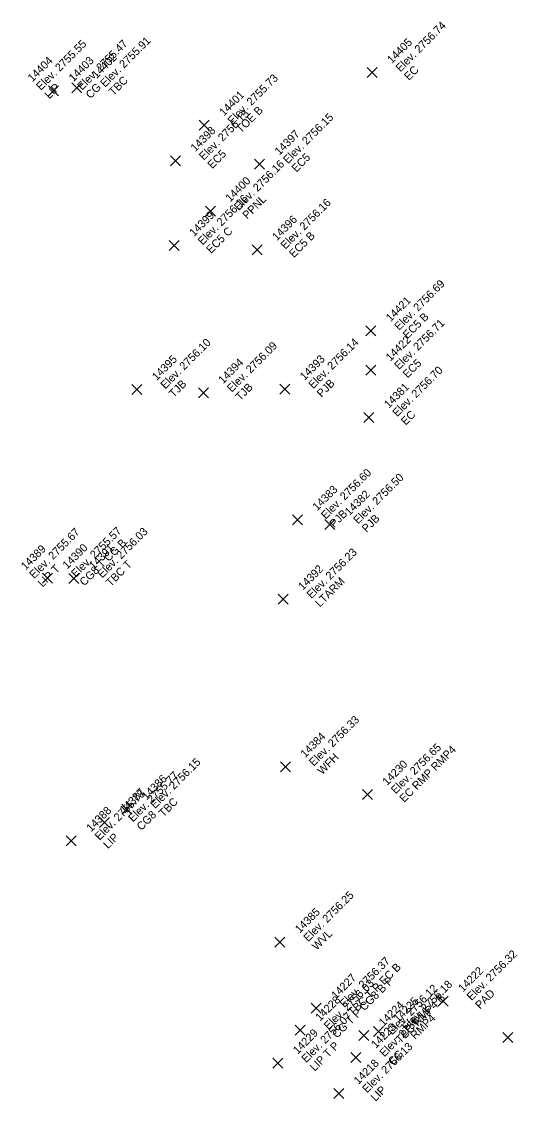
# Model space of a CAD drawing. Extents: x 2493999 to 2503109, y 700767 to 706646.
# Drawn here: x 2502320.41 to 2502335.28, y 703212 to 703244.38 of the extents above; entities that cross this region are included whole.
import ezdxf

# ---------------------------------------------------------------- set-up
doc = ezdxf.new("R2010")
doc.units = 0
doc.layers.add('ALG_CL_BLUE_Horiz', color=7, linetype='Continuous')
doc.layers.add('DES_SURFACE_Existing-Ground', color=7, linetype='Continuous')

msp = doc.modelspace()

# ---------------------------------------------------------------- linework, layer by layer
at = {"layer": 'ALG_CL_BLUE_Horiz'}
for points in [[(2502330.92, 703242.852), (2502330.77, 703243.002), (2502330.92, 703242.852), (2502330.77, 703242.702), (2502330.92, 703242.852), (2502331.07, 703242.702), (2502330.92, 703242.852), (2502331.07, 703243.002)], [(2502321.373, 703242.306), (2502321.223, 703242.456), (2502321.373, 703242.306), (2502321.223, 703242.156), (2502321.373, 703242.306), (2502321.523, 703242.156), (2502321.373, 703242.306), (2502321.523, 703242.456)], [(2502322.064, 703242.399), (2502321.914, 703242.549), (2502322.064, 703242.399), (2502321.914, 703242.249), (2502322.064, 703242.399), (2502322.214, 703242.249), (2502322.064, 703242.399), (2502322.214, 703242.549)], [(2502325.885, 703241.275), (2502325.735, 703241.425), (2502325.885, 703241.275), (2502325.735, 703241.125), (2502325.885, 703241.275), (2502326.035, 703241.125), (2502325.885, 703241.275), (2502326.035, 703241.425)], [(2502325.025, 703240.205), (2502324.875, 703240.355), (2502325.025, 703240.205), (2502324.875, 703240.055), (2502325.025, 703240.205), (2502325.175, 703240.055), (2502325.025, 703240.205), (2502325.175, 703240.355)], [(2502327.546, 703240.101), (2502327.396, 703240.251), (2502327.546, 703240.101), (2502327.396, 703239.951), (2502327.546, 703240.101), (2502327.696, 703239.951), (2502327.546, 703240.101), (2502327.696, 703240.251)], [(2502326.073, 703238.698), (2502325.923, 703238.848), (2502326.073, 703238.698), (2502325.923, 703238.548), (2502326.073, 703238.698), (2502326.223, 703238.548), (2502326.073, 703238.698), (2502326.223, 703238.848)], [(2502324.987, 703237.664), (2502324.837, 703237.814), (2502324.987, 703237.664), (2502324.837, 703237.514), (2502324.987, 703237.664), (2502325.137, 703237.514), (2502324.987, 703237.664), (2502325.137, 703237.814)], [(2502327.471, 703237.539), (2502327.321, 703237.689), (2502327.471, 703237.539), (2502327.321, 703237.389), (2502327.471, 703237.539), (2502327.621, 703237.389), (2502327.471, 703237.539), (2502327.621, 703237.689)], [(2502330.883, 703235.106), (2502330.733, 703235.256), (2502330.883, 703235.106), (2502330.733, 703234.956), (2502330.883, 703235.106), (2502331.033, 703234.956), (2502330.883, 703235.106), (2502331.033, 703235.256)], [(2502330.879, 703233.927), (2502330.729, 703234.077), (2502330.879, 703233.927), (2502330.729, 703233.777), (2502330.879, 703233.927), (2502331.029, 703233.777), (2502330.879, 703233.927), (2502331.029, 703234.077)], [(2502323.87, 703233.345), (2502323.72, 703233.495), (2502323.87, 703233.345), (2502323.72, 703233.195), (2502323.87, 703233.345), (2502324.02, 703233.195), (2502323.87, 703233.345), (2502324.02, 703233.495)], [(2502325.861, 703233.248), (2502325.711, 703233.398), (2502325.861, 703233.248), (2502325.711, 703233.098), (2502325.861, 703233.248), (2502326.011, 703233.098), (2502325.861, 703233.248), (2502326.011, 703233.398)], [(2502328.302, 703233.353), (2502328.152, 703233.503), (2502328.302, 703233.353), (2502328.152, 703233.203), (2502328.302, 703233.353), (2502328.452, 703233.203), (2502328.302, 703233.353), (2502328.452, 703233.503)], [(2502330.826, 703232.512), (2502330.676, 703232.662), (2502330.826, 703232.512), (2502330.676, 703232.362), (2502330.826, 703232.512), (2502330.976, 703232.362), (2502330.826, 703232.512), (2502330.976, 703232.662)], [(2502328.683, 703229.441), (2502328.533, 703229.591), (2502328.683, 703229.441), (2502328.533, 703229.291), (2502328.683, 703229.441), (2502328.833, 703229.291), (2502328.683, 703229.441), (2502328.833, 703229.591)], [(2502329.651, 703229.297), (2502329.501, 703229.447), (2502329.651, 703229.297), (2502329.501, 703229.147), (2502329.651, 703229.297), (2502329.801, 703229.147), (2502329.651, 703229.297), (2502329.801, 703229.447)], [(2502321.189, 703227.693), (2502321.039, 703227.843), (2502321.189, 703227.693), (2502321.039, 703227.543), (2502321.189, 703227.693), (2502321.339, 703227.543), (2502321.189, 703227.693), (2502321.339, 703227.843)], [(2502321.979, 703227.678), (2502321.829, 703227.828), (2502321.979, 703227.678), (2502321.829, 703227.528), (2502321.979, 703227.678), (2502322.129, 703227.528), (2502321.979, 703227.678), (2502322.129, 703227.828)], [(2502328.252, 703227.057), (2502328.102, 703227.207), (2502328.252, 703227.057), (2502328.102, 703226.907), (2502328.252, 703227.057), (2502328.402, 703226.907), (2502328.252, 703227.057), (2502328.402, 703227.207)], [(2502328.321, 703222.032), (2502328.171, 703222.182), (2502328.321, 703222.032), (2502328.171, 703221.882), (2502328.321, 703222.032), (2502328.471, 703221.882), (2502328.321, 703222.032), (2502328.471, 703222.182)], [(2502330.779, 703221.201), (2502330.629, 703221.351), (2502330.779, 703221.201), (2502330.629, 703221.051), (2502330.779, 703221.201), (2502330.929, 703221.051), (2502330.779, 703221.201), (2502330.929, 703221.351)], [(2502323.563, 703220.763), (2502323.413, 703220.913), (2502323.563, 703220.763), (2502323.413, 703220.613), (2502323.563, 703220.763), (2502323.713, 703220.613), (2502323.563, 703220.763), (2502323.713, 703220.913)], [(2502322.901, 703220.36), (2502322.751, 703220.51), (2502322.901, 703220.36), (2502322.751, 703220.21), (2502322.901, 703220.36), (2502323.051, 703220.21), (2502322.901, 703220.36), (2502323.051, 703220.51)], [(2502321.9, 703219.812), (2502321.75, 703219.962), (2502321.9, 703219.812), (2502321.75, 703219.662), (2502321.9, 703219.812), (2502322.05, 703219.662), (2502321.9, 703219.812), (2502322.05, 703219.962)], [(2502328.156, 703216.769), (2502328.006, 703216.919), (2502328.156, 703216.769), (2502328.006, 703216.619), (2502328.156, 703216.769), (2502328.306, 703216.619), (2502328.156, 703216.769), (2502328.306, 703216.919)], [(2502329.242, 703214.794), (2502329.092, 703214.944), (2502329.242, 703214.794), (2502329.092, 703214.644), (2502329.242, 703214.794), (2502329.392, 703214.644), (2502329.242, 703214.794), (2502329.392, 703214.944)], [(2502333.053, 703215.004), (2502332.903, 703215.154), (2502333.053, 703215.004), (2502332.903, 703214.854), (2502333.053, 703215.004), (2502333.203, 703214.854), (2502333.053, 703215.004), (2502333.203, 703215.154)], [(2502328.766, 703214.131), (2502328.616, 703214.281), (2502328.766, 703214.131), (2502328.616, 703213.981), (2502328.766, 703214.131), (2502328.916, 703213.981), (2502328.766, 703214.131), (2502328.916, 703214.281)], [(2502330.671, 703213.974), (2502330.521, 703214.124), (2502330.671, 703213.974), (2502330.521, 703213.824), (2502330.671, 703213.974), (2502330.821, 703213.824), (2502330.671, 703213.974), (2502330.821, 703214.124)], [(2502331.11, 703214.097), (2502330.96, 703214.247), (2502331.11, 703214.097), (2502330.96, 703213.947), (2502331.11, 703214.097), (2502331.26, 703213.947), (2502331.11, 703214.097), (2502331.26, 703214.247)], [(2502334.995, 703213.917), (2502334.845, 703214.067), (2502334.995, 703213.917), (2502334.845, 703213.767), (2502334.995, 703213.917), (2502335.145, 703213.767), (2502334.995, 703213.917), (2502335.145, 703214.067)], [(2502330.438, 703213.315), (2502330.288, 703213.465), (2502330.438, 703213.315), (2502330.288, 703213.165), (2502330.438, 703213.315), (2502330.588, 703213.165), (2502330.438, 703213.315), (2502330.588, 703213.465)], [(2502328.095, 703213.14), (2502327.945, 703213.29), (2502328.095, 703213.14), (2502327.945, 703212.99), (2502328.095, 703213.14), (2502328.245, 703212.99), (2502328.095, 703213.14), (2502328.245, 703213.29)], [(2502329.92, 703212.232), (2502329.77, 703212.382), (2502329.92, 703212.232), (2502329.77, 703212.082), (2502329.92, 703212.232), (2502330.07, 703212.082), (2502329.92, 703212.232), (2502330.07, 703212.382)]]:
    msp.add_lwpolyline(points, dxfattribs=at)

# ---------------------------------------------------------------- texts
at = {"layer": 'DES_SURFACE_Existing-Ground'}
for s, p in [('Elev. 2756.74', (2502331.769, 703242.852)), ('Elev. 2755.55', (2502320.99, 703242.3)), ('Elev. 2755.47', (2502322.222, 703242.306)), ('Elev. 2755.91', (2502322.913, 703242.399)), ('14405', (2502331.514, 703243.107)), ('14404', (2502320.735, 703242.555)), ('14403', (2502321.967, 703242.561)), ('14402', (2502322.658, 703242.654)), ('Elev. 2755.73', (2502326.734, 703241.275)), ('EC', (2502332.023, 703242.597)), ('LIP', (2502321.244, 703242.045)), ('CG', (2502322.476, 703242.051)), ('TBC', (2502323.167, 703242.144)), ('14401', (2502326.479, 703241.53)), ('TOE B', (2502326.988, 703241.02)), ('Elev. 2756.15', (2502325.874, 703240.205)), ('Elev. 2756.15', (2502328.395, 703240.101)), ('14398', (2502325.619, 703240.46)), ('14397', (2502328.14, 703240.356)), ('EC5', (2502326.128, 703239.95)), ('Elev. 2756.16', (2502326.922, 703238.698)), ('EC5', (2502328.649, 703239.846)), ('14400', (2502326.667, 703238.953)), ('Elev. 2756.16', (2502325.836, 703237.664)), ('PPNL', (2502327.176, 703238.443)), ('Elev. 2756.16', (2502328.32, 703237.539)), ('14399', (2502325.581, 703237.919)), ('14396', (2502328.065, 703237.794)), ('EC5 C', (2502326.09, 703237.409)), ('EC5 B', (2502328.574, 703237.284)), ('Elev. 2756.69', (2502331.732, 703235.106)), ('14421', (2502331.477, 703235.361)), ('EC5 B', (2502331.986, 703234.851)), ('Elev. 2756.71', (2502331.728, 703233.927)), ('Elev. 2756.10', (2502324.719, 703233.345)), ('Elev. 2756.09', (2502326.71, 703233.248)), ('Elev. 2756.14', (2502329.151, 703233.353)), ('14422', (2502331.473, 703234.182)), ('14395', (2502324.464, 703233.6)), ('14393', (2502328.896, 703233.608)), ('14394', (2502326.455, 703233.503)), ('Elev. 2756.70', (2502331.675, 703232.512)), ('EC5', (2502331.982, 703233.672)), ('TJB', (2502324.973, 703233.09)), ('TJB', (2502326.964, 703232.993)), ('PJB', (2502329.405, 703233.098)), ('14381', (2502331.42, 703232.767)), ('EC', (2502331.929, 703232.257)), ('Elev. 2756.60', (2502329.532, 703229.441)), ('Elev. 2756.50', (2502330.5, 703229.297)), ('14383', (2502329.277, 703229.696)), ('14382', (2502330.245, 703229.552)), ('PJB', (2502329.786, 703229.186)), ('PJB', (2502330.754, 703229.042)), ('Elev. 2755.67', (2502320.787, 703227.658)), ('Elev. 2755.57', (2502322.038, 703227.693)), ('Elev. 2756.03', (2502322.828, 703227.678)), ('CG8 T CG B', (2502322.292, 703227.438)), ('14389', (2502320.532, 703227.913)), ('14390', (2502321.783, 703227.948)), ('14391', (2502322.573, 703227.933)), ('Elev. 2756.23', (2502329.101, 703227.057)), ('TBC T', (2502323.082, 703227.423)), ('LIP T', (2502321.041, 703227.403)), ('14392', (2502328.846, 703227.312)), ('LTARM', (2502329.355, 703226.802)), ('Elev. 2756.33', (2502329.17, 703222.032)), ('14384', (2502328.915, 703222.287)), ('Elev. 2756.65', (2502331.628, 703221.201)), ('WFH', (2502329.424, 703221.777)), ('EC RMP RMP4', (2502331.882, 703220.946)), ('Elev. 2756.15', (2502324.412, 703220.763)), ('14230', (2502331.373, 703221.456)), ('Elev. 2755.77', (2502323.75, 703220.36)), ('14386', (2502324.157, 703221.018)), ('14387', (2502323.495, 703220.615)), ('Elev. 2755.78', (2502322.749, 703219.812)), ('TBC', (2502324.666, 703220.508)), ('14388', (2502322.494, 703220.067)), ('CG8', (2502324.004, 703220.105)), ('LIP', (2502323.003, 703219.557)), ('Elev. 2756.25', (2502329.005, 703216.769)), ('14385', (2502328.75, 703217.024)), ('WVL', (2502329.259, 703216.514)), ('Elev. 2756.37', (2502330.091, 703214.794)), ('Elev. 2756.32', (2502333.902, 703215.004)), ('TBC T P EC B', (2502330.345, 703214.539)), ('14222', (2502333.647, 703215.259)), ('Elev. 2756.03', (2502329.615, 703214.131)), ('14227', (2502329.836, 703215.049)), ('CG T P CG8 B P', (2502329.869, 703213.876)), ('Elev. 2756.18', (2502331.959, 703214.097)), ('Elev. 2756.12', (2502331.52, 703213.974)), ('PAD', (2502334.156, 703214.749)), ('14228', (2502329.36, 703214.386)), ('14224', (2502331.265, 703214.229)), ('14225', (2502331.704, 703214.352)), ('TBC RMP4 B', (2502331.774, 703213.719)), ('Elev. 2756.07', (2502328.944, 703213.14)), ('Elev. 2756.11', (2502331.287, 703213.315)), ('RMP4', (2502332.213, 703213.842)), ('14223', (2502331.032, 703213.57)), ('14229', (2502328.689, 703213.395)), ('LIP T P', (2502329.198, 703212.885)), ('Elev. 2756.13', (2502330.769, 703212.232)), ('CG', (2502331.541, 703213.06)), ('14218', (2502330.514, 703212.487)), ('LIP', (2502331.023, 703211.977))]:
    msp.add_text(s, height=0.24, rotation=45, dxfattribs=at).set_placement(p)

doc.saveas('drawing.dxf')
